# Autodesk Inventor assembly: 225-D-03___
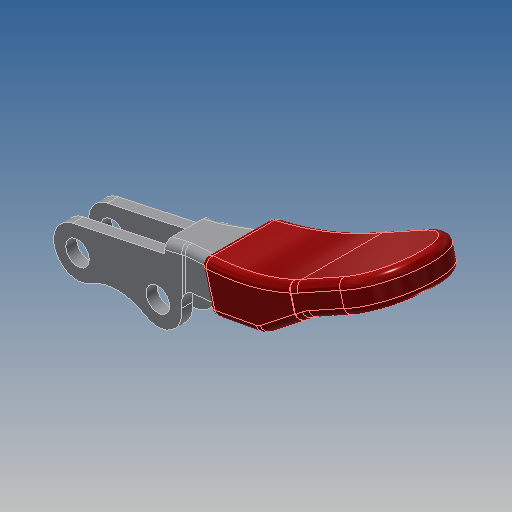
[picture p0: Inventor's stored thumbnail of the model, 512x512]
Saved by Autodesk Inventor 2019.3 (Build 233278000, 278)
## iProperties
Created: 2010-06
Part Number: 225-D-03___
Material: Ogólny
Document SubType Name: Assembly
Designer: CADENGINEERING4
Author: CADENGINEERING4
Revision Number: ANY
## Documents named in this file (3)
- E:\STRONA\Horizontal toggle clamp\CH-225-DSM\225-D-03___.iam
- E:\STRONA\Horizontal toggle clamp\CH-225-DSM\225-D-03___.ipt
- E:\STRONA\Horizontal toggle clamp\CH-225-DSM\1___.ipt
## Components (2 placed, 2 different names)
1. 225-D-03_??_15
2. 1_??_16
